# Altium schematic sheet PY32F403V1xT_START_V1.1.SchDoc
size B
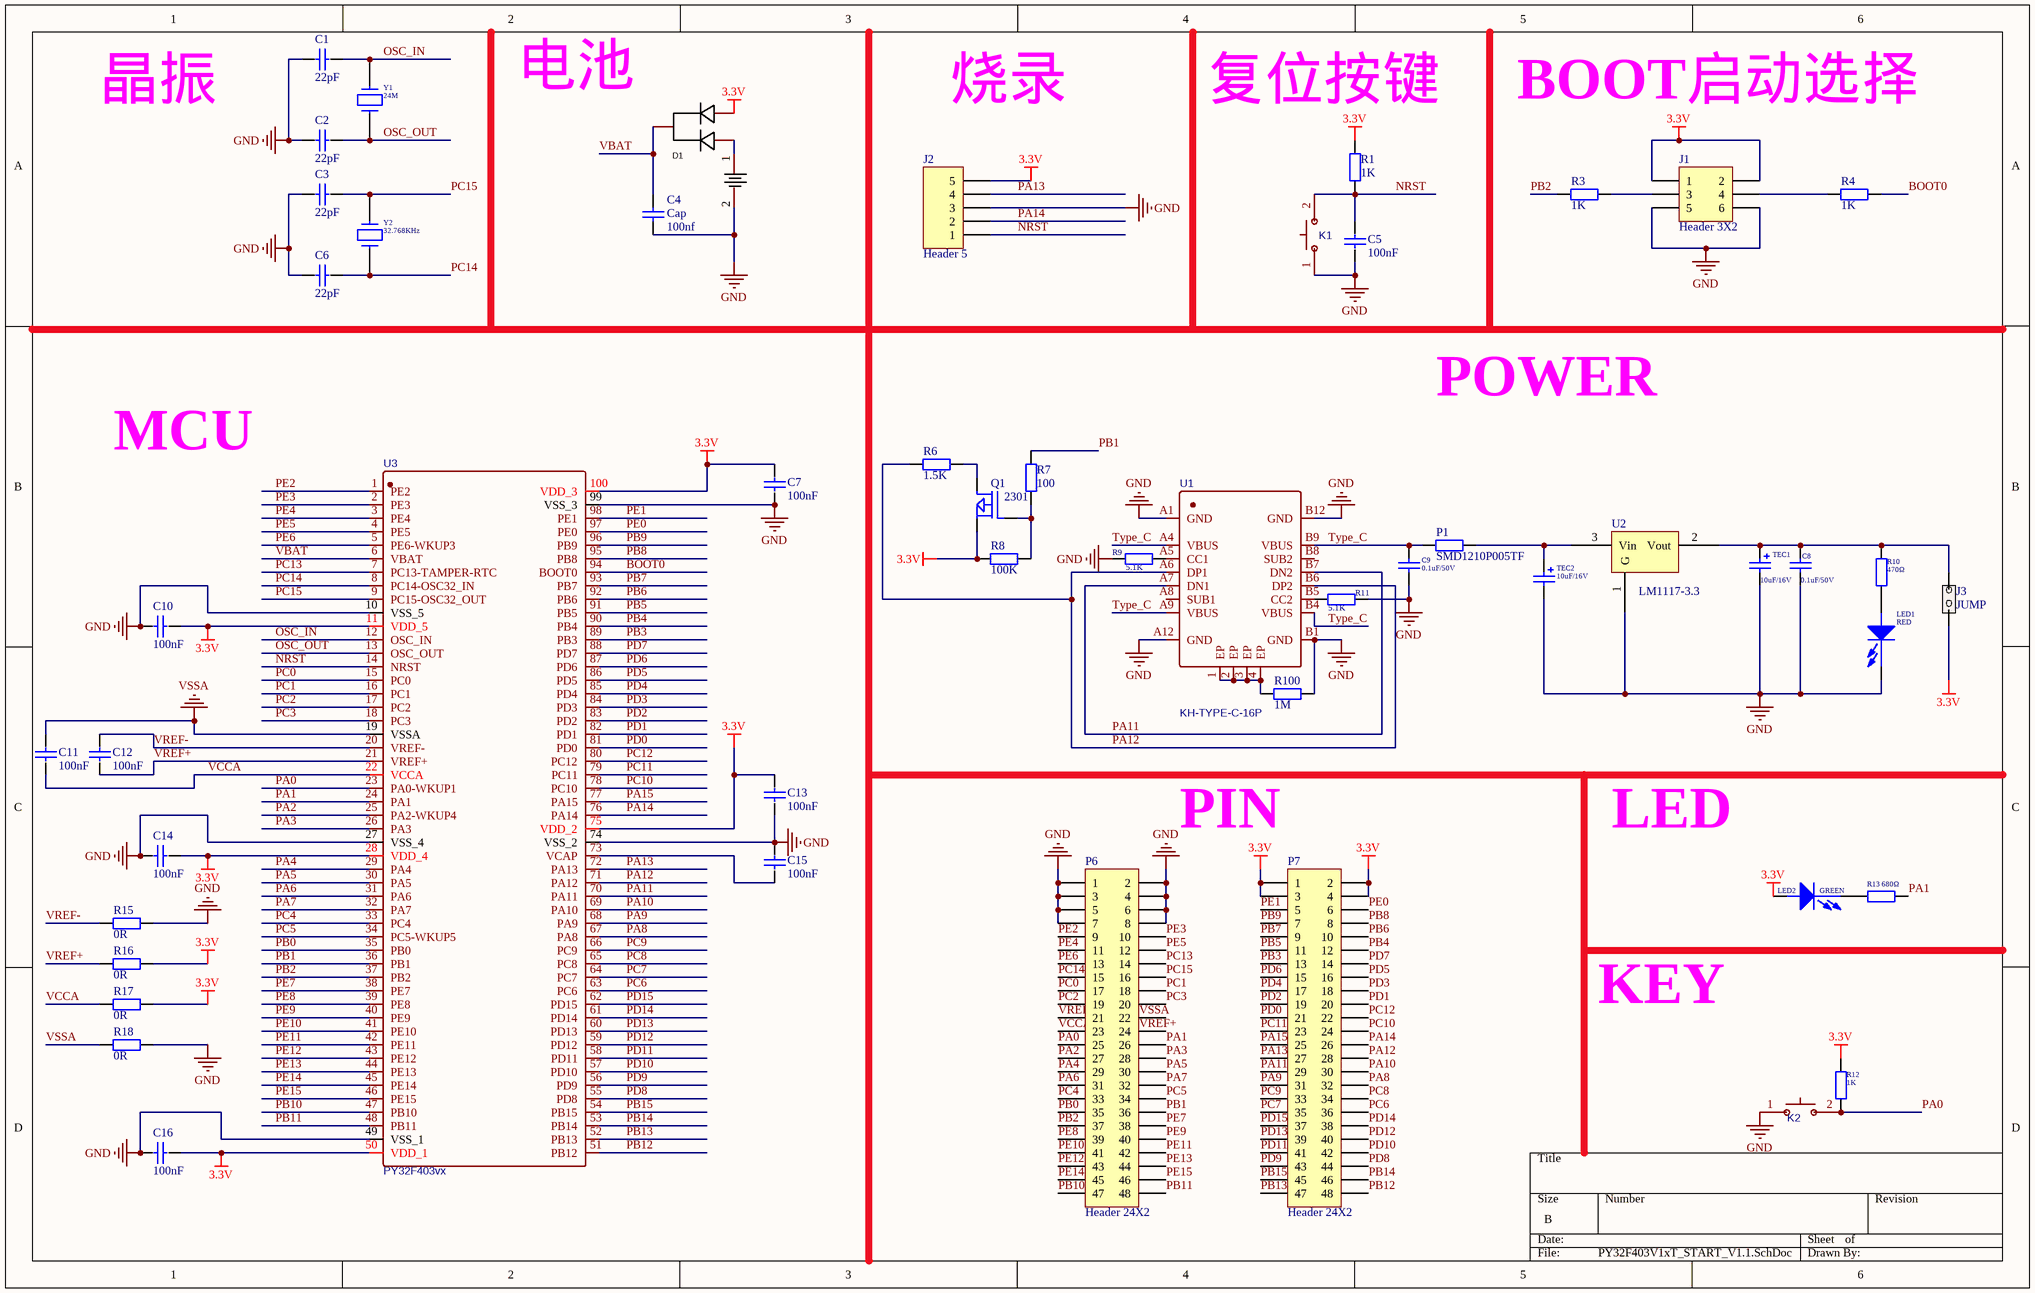
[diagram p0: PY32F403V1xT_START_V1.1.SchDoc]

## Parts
BAT1  KH-BS2032-2-1  [bat2]  (value not drawn)
C1  22pF  [c0603cap]
C2  22pF  [c0603cap]
C3  22pF  [c0603cap]
C4  Cap  value 100nf  [c0603cap]
C5  100nF  [c0603cap]
C6  22pF  [c0603cap]
C7  100nF  [c0603cap]
C8  0.1uF/50V  [c0603cap]
C9  0.1uF/50V  [c0603cap]
C10  100nF  [c0603cap]
C11  100nF  [c0603cap]
C12  100nF  [c0603cap]
C13  100nF  [c0603cap]
C14  100nF  [c0603cap]
C15  100nF  [c0603cap]
C16  100nF  [c0603cap]
D1  BAT54C_C2135  [肖特基二极管、]  (value not drawn)
J1  Header 3X2  [HDR2X3]
J2  Header 5  [HDR1X5]
J3  JUMP  [HDR1X2]
K1  1TS002B-2600-5001_key  [SW]  (value not drawn)
K2  1TS002B-2600-5001_key  [SW]  (value not drawn)
LED1  RED  [0603_LED]
LED2  GREEN  [0603_LED]
P1  SMD1210P005TF  [SDM1210P005TF]
P6  Header 24X2  [HDR2X24]
P7  Header 24X2  [HDR2X24]
Q1  2301  [SOT23 2301]
R1  value 1K  [0603R]  (hidden comment: Res)
R3  value 1K  [0603R]  (hidden comment: Res)
R4  value 1K  [0603R]  (hidden comment: Res)
R6  value 1.5K  [0603R]  (hidden comment: Res)
R7  value 100  [0603R]  (hidden comment: Res)
R8  value 100K  [0603R]  (hidden comment: Res)
R9  5.1K  [0603R]
R10  470Ω  [0603R]
R11  5.1K  [0603R]
R12  1K  [0603R]
R13  680Ω  [0603R]
R15  value 0R  [0603R]  (hidden comment: Res)
R16  value 0R  [0603R]  (hidden comment: Res)
R17  value 0R  [0603R]  (hidden comment: Res)
R18  value 0R  [0603R]  (hidden comment: Res)
R100  value 1M  [0805]  (hidden comment: Res)
TEC1  value 10uF/16V  [0603]  (hidden comment: 10uF)
TEC2  value 10uF/16V  [0603]  (hidden comment: 10uF)
U1  KH-TYPE-C-16P  [USB-C-SMD_KH-TYPE-C-16P]
U2  LM1117-3.3  [LM1117-3.3]
U3  PY32F403vx  [100PIN LQFP]
Y1  24M  [25MHZ_2]
Y2  32.768KHz  [32768KHZ_2]

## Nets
3.3V: C7.2 C10.2 C13.1 C14.1 C16.2 D1.2(A2) J1.1 J1.2 J2.5 J3.1 LED2.1(ANODE) P7.1 P7.2 P7.3 P7.4 Q1.2(S) R1.2 R8.2 R12.1 R16.2 R17.2 U3.11(VDD_5) U3.28(VDD_4) U3.50(VDD_1) U3.75(VDD_2) U3.100(VDD_3)
GND: BAT1.2 C1.2 C2.2 C3.2 C4.1 C5.1 C6.2 C7.1 C8.1 C9.1 C10.1 C13.2 C14.2 C15.2 C16.1 J1.5 J1.6 J2.3 K1.1(A) K2.1(A) LED1.2(CATHODE) P6.1 P6.2 P6.3 P6.4 P6.5 P6.6 P6.7 P6.8 R9.1 R11.2 R15.2 R18.2 R100.1 TEC1.2 TEC2.2 U1.A1(GND) U1.A12(GND) U1.B1(GND) U1.B12(GND) U2.1(G) U3.10(VSS_5) U3.27(VSS_4) U3.49(VSS_1) U3.74(VSS_2) U3.99(VSS_3)
VSSA: C11.2 P6.22 R18.1 U3.19(VSSA)
BOOT0: R4.1 U3.94(BOOT0)
NRST: C5.2 J2.1 K1.2(B) R1.1 U3.14(NRST)
OSC_IN: C1.1 U3.12(OSC_IN) Y1.2
OSC_OUT: C2.1 U3.13(OSC_OUT) Y1.1
PA0: K2.2(B) P6.25 R12.2 U3.23(PA0-WKUP1)
PA1: P6.26 R13.2 U3.24(PA1)
PA2: P6.27 U3.25(PA2-WKUP4)
PA3: P6.28 U3.26(PA3)
PA4: P6.29 U3.29(PA4)
PA5: P6.30 U3.30(PA5)
PA6: P6.31 U3.31(PA6)
PA7: P6.32 U3.32(PA7)
PA8: P7.32 U3.67(PA8)
PA9: P7.31 U3.68(PA9)
PA10: P7.30 U3.69(PA10)
PA11: P7.29 U1.A7(DN1) U1.B7(DN2) U3.70(PA11)
PA12: P7.28 R6.1 U1.A6(DP1) U1.B6(DP2) U3.71(PA12)
PA13: J2.4 P7.27 U3.72(PA13)
PA14: J2.2 P7.26 U3.76(PA14)
PA15: P7.25 U3.77(PA15)
PB0: P6.35 U3.35(PB0)
PB1: P6.36 R7.1 U3.36(PB1)
PB2: P6.37 R3.2 U3.37(PB2)
PB3: P7.13 U3.89(PB3)
PB4: P7.12 U3.90(PB4)
PB5: P7.11 U3.91(PB5)
PB6: P7.10 U3.92(PB6)
PB7: P7.9 U3.93(PB7)
PB8: P7.8 U3.95(PB8)
PB9: P7.7 U3.96(PB9)
PB10: P6.47 U3.47(PB10)
PB11: P6.48 U3.48(PB11)
PB12: P7.48 U3.51(PB12)
PB13: P7.47 U3.52(PB13)
PB14: P7.46 U3.53(PB14)
PB15: P7.45 U3.54(PB15)
PC0: P6.17 U3.15(PC0)
PC1: P6.18 U3.16(PC1)
PC2: P6.19 U3.17(PC2)
PC3: P6.20 U3.18(PC3)
PC4: P6.33 U3.33(PC4)
PC5: P6.34 U3.34(PC5-WKUP5)
PC6: P7.36 U3.63(PC6)
PC7: P7.35 U3.64(PC7)
PC8: P7.34 U3.65(PC8)
PC9: P7.33 U3.66(PC9)
PC10: P7.24 U3.78(PC10)
PC11: P7.23 U3.79(PC11)
PC12: P7.22 U3.80(PC12)
PC13: P6.14 U3.7(PC13-TAMPER-RTC)
PC14: C6.1 P6.15 U3.8(PC14-OSC32_IN) Y2.2
PC15: C3.1 P6.16 U3.9(PC15-OSC32_OUT) Y2.1
PD0: P7.21 U3.81(PD0)
PD1: P7.20 U3.82(PD1)
PD2: P7.19 U3.83(PD2)
PD3: P7.18 U3.84(PD3)
PD4: P7.17 U3.85(PD4)
PD5: P7.16 U3.86(PD5)
PD6: P7.15 U3.87(PD6)
PD7: P7.14 U3.88(PD7)
PD8: P7.44 U3.55(PD8)
PD9: P7.43 U3.56(PD9)
PD10: P7.42 U3.57(PD10)
PD11: P7.41 U3.58(PD11)
PD12: P7.40 U3.59(PD12)
PD13: P7.39 U3.60(PD13)
PD14: P7.38 U3.61(PD14)
PD15: P7.37 U3.62(PD15)
PE0: P7.6 U3.97(PE0)
PE1: P7.5 U3.98(PE1)
PE2: P6.9 U3.1(PE2)
PE3: P6.10 U3.2(PE3)
PE4: P6.11 U3.3(PE4)
PE5: P6.12 U3.4(PE5)
PE6: P6.13 U3.5(PE6-WKUP3)
PE7: P6.38 U3.38(PE7)
PE8: P6.39 U3.39(PE8)
PE9: P6.40 U3.40(PE9)
PE10: P6.41 U3.41(PE10)
PE11: P6.42 U3.42(PE11)
PE12: P6.43 U3.43(PE12)
PE13: P6.44 U3.44(PE13)
PE14: P6.45 U3.45(PE14)
PE15: P6.46 U3.46(PE15)
Type_C: C9.2 P1.1 U1.A4(VBUS) U1.A9(VBUS) U1.B4(VBUS) U1.B9(VBUS)
VBAT: C4.2 D1.3(K) U3.6(VBAT)
VCCA: C11.1 P6.23 R17.1 U3.22(VCCA)
VREF+: C12.2 P6.24 R16.1 U3.21(VREF+)
VREF-: C12.1 P6.21 R15.1 U3.20(VREF-)
NetBAT1_1: BAT1.1 D1.1(A1)
NetC8_2: C8.2 J3.2 R10.1 TEC1.1 U2.2(Vout)
NetC15_1: C15.1 U3.73(VCAP)
NetJ1_3: J1.3 R3.1
NetJ1_4: J1.4 R4.2
NetLED1_1: LED1.1(ANODE) R10.2
NetLED2_2: LED2.2(CATHODE) R13.1
NetP1_2: P1.2 TEC2.1 U2.3(Vin)
NetQ1_1: Q1.1(G) R7.2 R8.1
NetQ1_3: Q1.3(D) R6.2
NetR9_2: R9.2 U1.A5(CC1)
NetR11_1: R11.1 U1.B5(CC2)
NetR100_2: R100.2 U1.1(EP) U1.2(EP) U1.3(EP) U1.4(EP)

Not connected (* = marked no-connect by the designer): U1 A8(SUB1) B8(SUB2)

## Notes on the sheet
- 电池
- 晶振
- 烧录
- (near R1) 复位按键
- BOOT启动选择
- POWER
- MCU
- PIN
- LED
- KEY

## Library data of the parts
BAT1 = KH-BS2032-2-1: Manufacturer: kinghelm(金航标); Add into BOM: yes
C1-C3 C5-C7 C10-C16 = C0603: PCB DECAL: 0603
C4 C8 = Cap: Capacitor
C9 = CAP: Capacitor; Value: 2.2uF
D1 = BAT54C_C2135: Manufacturer: CJ(江苏长电/长晶); Name: BAT54C; Add into BOM: yes; Reverse Voltage (Vr): 30V; Average Rectified Current (Io): 200mA; Forward Voltage (Vf@If): 1V@100mA
J1 = Header 3X2: Header, 3-Pin, Dual row
J2 = Header 5: Header, 5-Pin
K1 K2 = 1TS002B-2600-5001_key: BOM_Manufacturer: HYP; Contributor: LCSC
LED1 LED2 = PDI-E803_Dup1
P6 P7 = Header 24X2: Header, 24-Pin, Dual row
Q1 = MOSFET P: Value: SI2301; 器件封装(外观): SOT23
R1 R3 R4 R6-R8 R15-R18 R100 = Res: Resistor; 器件封装(外观): 0603
R9 R11 = Res_1: Resistor; 器件封装(外观): 0603; Value: 10K
R10 R12 R13 = Res: Resistor; 器件封装(外观): 0603; Value: 10K
TEC1 TEC2 = 贴片钽电容: 器件封装(外观): 3528
U1 = KH-TYPE-C-16P: BOM_Manufacturer: Shenzhen Kinghelm Elec; Contributor: LCSC
U3 = PY32F403vx_LQFP100: BOM_Manufacturer: ST; BOM_Manufacturer Part: STM32F103VCT6; subpart_no: 2; tags: STM32
Y1 = CRYSTAL: Value: X503225MSB2GI
Y2 = CRYSTAL_1: Crystal; Value: X503225MSB2GI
